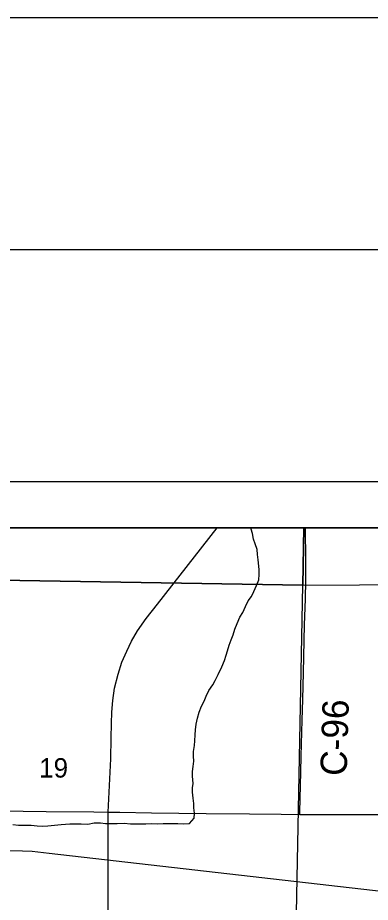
# Model space of a CAD drawing. Extents: x -9.1 to 34, y -3.1 to 22.
# Drawn here: x 2.64 to 3.4, y 20.093 to 22 of the extents above; entities that cross this region are included whole.
import ezdxf

# ---------------------------------------------------------------- set-up
doc = ezdxf.new("R2010")
doc.units = 0
for name, color, linetype in [('GM_X_County_Road', 7, 'Continuous'), ('GM_X_County_Road_Text', 7, 'Continuous'), ('GM_X_Minor_River', 7, 'Continuous'), ('GM_X_Rail_Line', 7, 'Continuous'), ('GM_X_Section', 7, 'Continuous'), ('GM_X_Section_Text', 7, 'Continuous'), ('SH_Border', 7, 'Continuous'), ('SH_Cut_Line', 7, 'Continuous'), ('SH_Data', 7, 'Continuous')]:
    doc.layers.add(name, color=color, linetype=linetype)

msp = doc.modelspace()

# ---------------------------------------------------------------- linework, layer by layer
at = {"layer": 'GM_X_County_Road'}
for points in [[(2.835, 20.2873), (2.8407, 20.4023), (2.8417, 20.4468), (2.842, 20.4783), (2.8429, 20.5028), (2.845, 20.5279), (2.8489, 20.5545), (2.8565, 20.5847), (2.8643, 20.6108), (2.8749, 20.6344), (2.8852, 20.6558), (2.8979, 20.6779), (2.917, 20.7048), (2.9415, 20.7357), (3.0695, 20.9)], [(3.2478, 20.2825), (3.2479, 20.287), (3.2502, 20.3745), (3.2509, 20.4083), (3.253, 20.4857), (3.2543, 20.53), (3.2557, 20.5884), (3.2582, 20.6908), (3.2597, 20.7467), (3.2606, 20.7871), (3.2605, 20.8461), (3.2603, 20.8834), (3.2602, 20.9)], [(2.6, 20.2901), (2.6022, 20.2901), (2.7016, 20.2889), (2.8041, 20.2878), (2.835, 20.2873), (2.86, 20.2869), (2.9283, 20.2859), (2.9873, 20.2854), (3.0464, 20.2847), (3.1396, 20.2836), (3.2079, 20.2826), (3.2478, 20.2825)], [(2.835, 20.1618), (2.835, 20.2873)], [(3.2478, 20.2825), (3.2855, 20.2824), (3.3849, 20.2819), (3.4657, 20.2822), (3.5092, 20.2824), (3.5465, 20.2825), (3.6676, 20.2834), (3.7422, 20.2839), (3.7826, 20.2841), (3.882, 20.2846), (3.9503, 20.2852), (3.9814, 20.2856), (4.0186, 20.2856), (4.0714, 20.2861), (4.1211, 20.2865), (4.1676, 20.2869), (4.1717, 20.287), (4.1804, 20.2872), (4.191, 20.2875)], [(2.8108, 19.8028), (2.8114, 19.8187), (2.8132, 19.8366), (2.8156, 19.8478), (2.8196, 19.8623), (2.8238, 19.8771), (2.8271, 19.8926), (2.8302, 19.9119), (2.8326, 19.9271), (2.8341, 19.9476), (2.8341, 19.9658), (2.835, 19.9891), (2.835, 20.1618)]]:
    msp.add_lwpolyline(points, dxfattribs=at)
at = {"layer": 'GM_X_Minor_River'}
msp.add_lwpolyline([(2.6295, 20.2609), (2.6419, 20.2595), (2.6544, 20.2589), (2.6688, 20.2594), (2.682, 20.2577), (2.6937, 20.2567), (2.705, 20.2577), (2.7194, 20.259), (2.7338, 20.261), (2.7524, 20.2618), (2.7622, 20.2624), (2.7769, 20.2618), (2.7913, 20.2611), (2.8046, 20.2639), (2.8186, 20.2644), (2.8291, 20.2628), (2.8435, 20.2625), (2.8541, 20.2627), (2.8692, 20.2632), (2.8828, 20.2622), (2.8934, 20.262), (2.904, 20.2622), (2.9161, 20.2624), (2.9289, 20.2626), (2.9406, 20.2623), (2.9531, 20.2625), (2.9633, 20.2631), (2.9754, 20.2625), (2.9853, 20.2627), (2.997, 20.2618), (3.0098, 20.2627), (3.0199, 20.2746), (3.0208, 20.2852), (3.0198, 20.2966), (3.0196, 20.3061), (3.0183, 20.3171), (3.0166, 20.33), (3.0168, 20.3395), (3.0181, 20.3493), (3.0168, 20.3645), (3.0166, 20.3748), (3.0179, 20.3857), (3.0196, 20.3971), (3.019, 20.4081), (3.0185, 20.4183), (3.0209, 20.4312), (3.0215, 20.441), (3.0224, 20.4539), (3.023, 20.4645), (3.0243, 20.4766), (3.0272, 20.4902), (3.0312, 20.503), (3.0359, 20.5158), (3.0414, 20.5267), (3.0461, 20.5373), (3.0516, 20.5493), (3.0605, 20.5617), (3.0656, 20.5714), (3.0719, 20.5842), (3.0801, 20.6004), (3.0852, 20.6143), (3.0892, 20.6256), (3.092, 20.6354), (3.0956, 20.6471), (3.0999, 20.6588), (3.1043, 20.6693), (3.1075, 20.6818), (3.1126, 20.6942), (3.1189, 20.7074), (3.1247, 20.7175), (3.131, 20.7307), (3.1365, 20.7427), (3.1435, 20.7524), (3.1489, 20.7633), (3.1548, 20.7761), (3.1592, 20.7882), (3.1605, 20.7999), (3.1603, 20.8105), (3.1584, 20.831), (3.1563, 20.8424), (3.1557, 20.8538), (3.1518, 20.8657), (3.1478, 20.8756), (3.1461, 20.8877), (3.1428, 20.8976), (3.1423, 20.9)], dxfattribs=at)
at = {"layer": 'GM_X_Rail_Line'}
msp.add_lwpolyline([(2.6, 20.2062), (2.6188, 20.2048), (2.6502, 20.2037), (2.671, 20.2028), (2.7079, 20.1988), (3.6242, 20.0941), (3.9983, 20.0517), (4.1941, 20.0298), (4.219, 20.0279), (4.2423, 20.0262), (4.2931, 20.0256), (4.3579, 20.026), (4.3853, 20.0269), (4.4001, 20.0265), (4.4445, 20.0235)], dxfattribs=at)
at = {"layer": 'GM_X_Section'}
msp.add_line((4.2302, 20.9), (3.2563, 20.9), dxfattribs=at)
for points in [[(3.2563, 20.9), (2.6, 20.9), (2.6, 20.7875)], [(2.6, 20.7875), (3.2541, 20.7764), (3.2563, 20.9)], [(3.2563, 20.9), (3.2541, 20.7764), (4.2289, 20.7827), (4.2302, 20.9)], [(2.6, 19.7778), (3.2347, 19.7726), (3.2541, 20.7764), (2.6, 20.7875)]]:
    msp.add_lwpolyline(points, dxfattribs=at)
msp.add_lwpolyline([(3.2541, 20.7764), (4.2289, 20.7827), (4.2285, 19.7772), (3.2347, 19.7726)], close=True, dxfattribs=at)
at = {"layer": 'SH_Border'}
msp.add_lwpolyline([(2, 21.5), (33.5, 21.5), (33.5, 0.5), (2, 0.5)], close=True, dxfattribs=at)
at = {"layer": 'SH_Cut_Line'}
msp.add_lwpolyline([(0, 0), (34, 0), (34, 22), (0, 22)], close=True, dxfattribs=at)
at = {"layer": 'SH_Data'}
for p, q in [((2.5, 21), (9.5, 21)), ((2.6, 20.9), (9.4, 20.9))]:
    msp.add_line(p, q, dxfattribs=at)

# ---------------------------------------------------------------- texts
at = {"layer": 'GM_X_County_Road_Text'}
msp.add_text('C-96', height=0.05682, rotation=88.2856, dxfattribs=at).set_placement((3.3487, 20.3648))
at = {"layer": 'GM_X_Section_Text'}
msp.add_text('19', height=0.04186, rotation=0, dxfattribs=at).set_placement((2.6863, 20.3618))

doc.saveas('drawing.dxf')
